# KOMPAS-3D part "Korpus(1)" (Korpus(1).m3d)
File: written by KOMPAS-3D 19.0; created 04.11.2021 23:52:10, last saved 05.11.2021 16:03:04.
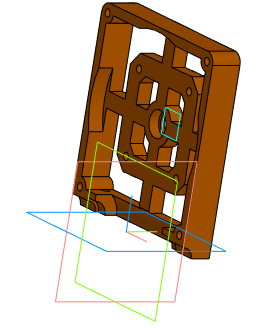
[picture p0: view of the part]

Document properties: Полное имя файла: D:\3D_print\3D проекты Компас 3D\Редуктор (Снова)\Korpus(1).m3d

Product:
- Part/product: Korpus(1)
    Материал: АБС 0603Т ТУ 2214-019-002 03521-96 (density 0 kg/m3)

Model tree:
1. Смещенная плоскость:1  (labels: Подшипник 23 ГОСТ 8338-75\Наружное кольцо; Korpus(1); Операция вращения:1; Операция вращения:1)
     Расстояние = 1.6
2. Эскиз:2  (labels: Подшипник 23 ГОСТ 8338-75\Наружное кольцо; Korpus(1); Скругление:2; Скругление:2)
3. Элемент выдавливания:1  (labels: Korpus(1))
     Расстояние 1 = 11.5
4. Эскиз:3  (labels: Korpus(1))
5. Элемент выдавливания:2
     Расстояние 1 = 34.6; Расстояние 2 = 34.6
6. Эскиз:4  (labels: Korpus(1))
7. Элемент выдавливания:3  (labels: Подшипник 23 ГОСТ 8338-75\Наружное кольцо; Korpus(1); Операция вращения:1; Операция вращения:1)
     Расстояние 1 = 25; Смещение 1 = 0.1; Расстояние 2 = 25; Смещение 2 = 0.1
8. Эскиз:6  (with: Эскиз:1)  (labels: Korpus(1))
9. Элемент выдавливания:5  (labels: Подшипник 23 ГОСТ 8338-75\Наружное кольцо; Korpus(1); Операция вращения:1; Операция вращения:1)
     Расстояние 2 = 5.9
10. Эскиз:9  (with: Элемент выдавливания:5)
11. Элемент выдавливания:8  (with: Элемент выдавливания:1)
     Расстояние 2 = 4; Смещение 2 = 1.6
12. Эскиз:10  (with: Элемент выдавливания:1)  (labels: Гайка М3-6H ГОСТ 5915-70; Korpus(1); Фаска:3; Фаска:3)
13. Элемент выдавливания:9
     Расстояние 2 = 11.5
14. Эскиз:12  (with: Элемент выдавливания:1, Элемент выдавливания:2)  (labels: Гайка М3-6H ГОСТ 5915-70; Korpus(1); Фаска:3; Фаска:3)
15. Элемент выдавливания:10
     Расстояние 2 = 11.5
16. Эскиз:13  (with: Элемент выдавливания:1)  (labels: Korpus(1))
17. Элемент выдавливания:11  (labels: Подшипник 23 ГОСТ 8338-75\Наружное кольцо; Korpus(1); Операция вращения:1; Операция вращения:1)
     Расстояние 1 = 20.9; Расстояние 2 = 20.9
18. Скругление:2  (with: Элемент выдавливания:1)
     Радиус = 4
19. Эскиз:15  (with: Элемент выдавливания:1, Элемент выдавливания:2)
20. Элемент выдавливания:12  (with: Элемент выдавливания:10, Эскиз:16, Элемент выдавливания:5)  (labels: Переходник на Nema_17; Reductor\Korpus(1))
     Расстояние 2 = 7.41561
21. Элемент выдавливания:13  (with: Элемент выдавливания:5)  (labels: АБС 0603Т ТУ 2214-019-002 03521-96)
     Расстояние 1 = -5.6

Referenced files in D:\3D_print\3D проекты Компас 3D\Редуктор (Снова)\: R-10 - Reductor.a3d
Referenced files in D:\3D_print\3D проекты Компас 3D\Халява Projects 5\: Намоточный станок (Projects 6).a3d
